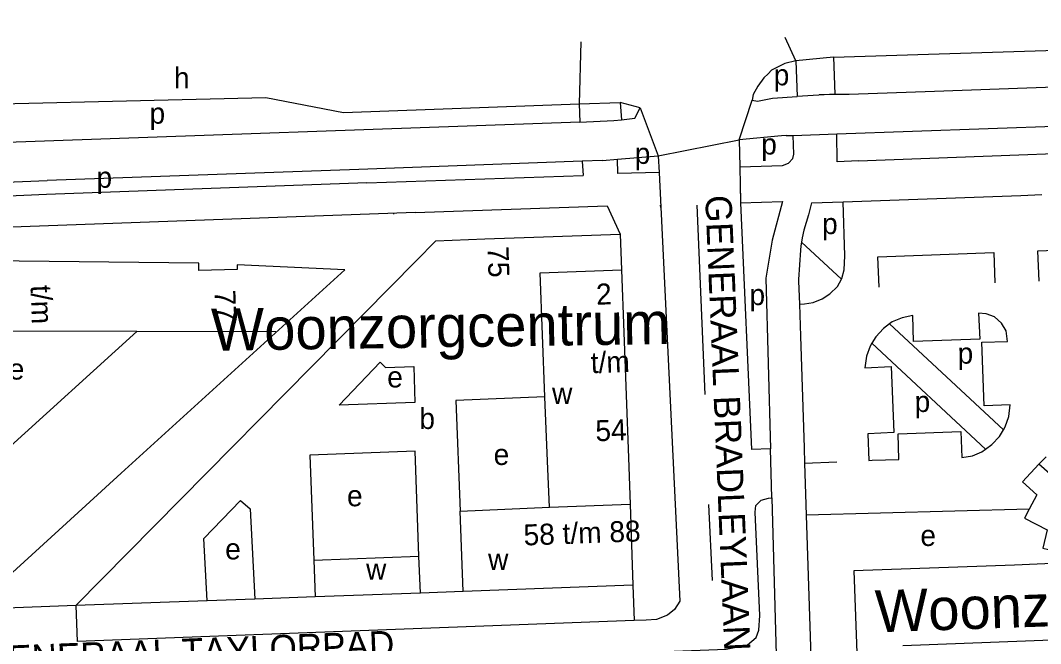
# Model space of a CAD drawing. Extents: x 159294 to 161936, y 384538 to 386517.
# Drawn here: x 161217.5 to 161411.8, y 386380.5 to 386499.3 of the extents above; entities that cross this region are included whole.
import ezdxf

# ---------------------------------------------------------------- set-up
doc = ezdxf.new("R2010")
doc.units = 0
for name, color, linetype in [('BLT_Basislijn', 7, 'Continuous'), ('BLT_Bebouwing', 7, 'Continuous'), ('BLT_Bebouwing_beschrifting', 7, 'Continuous'), ('BLT_Centroide', 7, 'Continuous'), ('BLT_Huisnummer_reeks', 7, 'Continuous'), ('BLT_Onderdoorgang_en_onderverdeling', 7, 'Continuous'), ('BLT_Onderverdeling_panden', 7, 'Continuous'), ('BLT_Straatnaam', 7, 'Continuous'), ('BLT_Vlakafsluiter', 7, 'Continuous')]:
    doc.layers.add(name, color=color, linetype=linetype)

msp = doc.modelspace()

# ---------------------------------------------------------------- linework, layer by layer
at = {"layer": 'BLT_Basislijn'}
for p, q in [((161372.32, 386492.27), (161365.2, 386491.56)), ((161365.2, 386491.56), (161365.4, 386484.75)), ((161372.32, 386492.27), (161372.58, 386485.17)), ((161359.9, 386489.08), (161360.56, 386489.75)), ((161391.6, 386485.79), (161500, 386489.72)), ((161372.58, 386485.17), (161365.4, 386484.75)), ((161369.65, 386485.15), (161372.58, 386485.17)), ((161323.9, 386483.33), (161331.75, 386483.6)), ((161356.83, 386484.07), (161357.87, 386483.84)), ((161324.03, 386479.85), (161174.09, 386474.55)), ((161330.52, 386480.19), (161331.96, 386480.27)), ((161373.01, 386477.62), (161424.25, 386479.43)), ((161363.33, 386477.28), (161364.7, 386477.33)), ((161364.7, 386477.33), (161373.01, 386477.62)), ((161354.38, 386476.46), (161354.5, 386471.33)), ((161331.18, 386472.78), (161338.98, 386473.45)), ((161324.51, 386472.4), (161281.95, 386470.85)), ((161328.38, 386472.54), (161324.51, 386472.4)), ((161324.51, 386472.4), (161324.65, 386469.66)), ((161328.38, 386472.54), (161331.18, 386472.78)), ((161354.5, 386471.33), (161354.66, 386464.49)), ((161281.95, 386470.85), (161222.58, 386468.71)), ((161283.47, 386468.31), (161324.65, 386469.66)), ((161339.13, 386470.29), (161343.07, 386388.54)), ((161283.47, 386468.31), (161222.43, 386466.04)), ((161354.58, 386468.28), (161354.66, 386464.49)), ((161354.58, 386468.28), (161354.66, 386464.49)), ((161374.22, 386464.69), (161408.02, 386465.9)), ((161408.02, 386465.9), (161412.02, 386466.04)), ((161292.69, 386462.61), (161329.27, 386463.89)), ((161292.69, 386462.61), (161329.27, 386463.89)), ((161292.69, 386462.61), (161329.27, 386463.89)), ((161339.45, 386463.6), (161339.38, 386464.02)), ((161346.3, 386464.05), (161347.82, 386427.93)), ((161368.17, 386464.48), (161367.62, 386462.2)), ((161368.17, 386464.48), (161374.22, 386464.69)), ((161374.49, 386454.39), (161374.22, 386464.69)), ((161292.69, 386462.61), (161217.61, 386459.92)), ((161292.69, 386462.61), (161217.61, 386459.92)), ((161292.69, 386462.61), (161217.61, 386459.92)), ((161288.46, 386462.46), (161288.68, 386462.47)), ((161288.46, 386462.46), (161288.68, 386462.47)), ((161288.46, 386462.46), (161288.68, 386462.47)), ((161217.61, 386459.92), (161153.14, 386457.6)), ((161366.28, 386457.01), (161373.87, 386449.95)), ((161411.29, 386455.33), (161425.23, 386455.84)), ((161374.39, 386451.68), (161374.49, 386454.39)), ((161380.81, 386454.17), (161402.9, 386455.04)), ((161381.04, 386448.43), (161380.81, 386454.17)), ((161402.9, 386455.04), (161403.11, 386449.22)), ((161411.51, 386449.56), (161411.29, 386455.33)), ((161373.1, 386448.56), (161373.87, 386449.95)), ((161373.87, 386449.95), (161373.94, 386450.08)), ((161373.94, 386450.08), (161374.39, 386451.68)), ((161365.7, 386449.53), (161365.85, 386445.14)), ((161371.64, 386447.13), (161373.1, 386448.56)), ((161368.48, 386445.48), (161370.22, 386446.19)), ((161370.22, 386446.19), (161371.64, 386447.13)), ((161365.85, 386445.14), (161366.84, 386445.22)), ((161365.85, 386445.14), (161366.05, 386439.08)), ((161366.84, 386445.22), (161368.48, 386445.48)), ((161385.4, 386442.58), (161383.54, 386441.77)), ((161387.44, 386443.01), (161385.4, 386442.58)), ((161387.62, 386438.05), (161387.44, 386443.01)), ((161401.44, 386443.33), (161399.97, 386443.46)), ((161399.97, 386443.46), (161400.2, 386438.5)), ((161403.01, 386442.72), (161401.44, 386443.33)), ((161404.36, 386441.53), (161403.01, 386442.72)), ((161381.85, 386440.54), (161380.43, 386438.95)), ((161383.04, 386441.41), (161381.85, 386440.54)), ((161383.54, 386441.77), (161383.04, 386441.41)), ((161383.04, 386441.41), (161404.72, 386421.21)), ((161405.22, 386440.07), (161404.36, 386441.53)), ((161380.43, 386438.95), (161379.66, 386437.72)), ((161400.2, 386438.5), (161387.62, 386438.05)), ((161405.52, 386438.03), (161405.22, 386440.07)), ((161379.31, 386437.16), (161378.61, 386435.22)), ((161379.66, 386437.72), (161379.31, 386437.16)), ((161379.66, 386437.72), (161401.31, 386417.55)), ((161400.58, 386437.89), (161405.52, 386438.03)), ((161401.02, 386425.81), (161400.58, 386437.89)), ((161378.61, 386435.22), (161378.35, 386433.04)), ((161378.35, 386433.04), (161383.31, 386433.27)), ((161383.31, 386433.27), (161383.85, 386420.7)), ((161405.98, 386425.98), (161401.02, 386425.81)), ((161405.72, 386423.73), (161405.98, 386425.98)), ((161405.06, 386421.79), (161405.72, 386423.73)), ((161383.85, 386420.7), (161378.89, 386420.46)), ((161384.65, 386420.47), (161396.61, 386420.89)), ((161396.61, 386420.89), (161396.8, 386415.95)), ((161403.96, 386419.95), (161404.72, 386421.21)), ((161404.72, 386421.21), (161405.06, 386421.79)), ((161378.89, 386420.46), (161379.08, 386415.39)), ((161384.78, 386415.53), (161384.65, 386420.47)), ((161402.48, 386418.44), (161403.96, 386419.95)), ((161360.59, 386408.26), (161360.34, 386417.57)), ((161398.83, 386416.25), (161400.6, 386417)), ((161400.6, 386417), (161401.31, 386417.55)), ((161401.31, 386417.55), (161402.48, 386418.44)), ((161366.85, 386414.85), (161372.99, 386415.11)), ((161366.85, 386414.85), (161367.04, 386408.93)), ((161379.08, 386415.39), (161379.69, 386415.42)), ((161379.69, 386415.42), (161384.78, 386415.53)), ((161396.8, 386415.95), (161398.83, 386416.25)), ((161412.83, 386416.07), (161411.48, 386414.68)), ((161360.59, 386408.26), (161361.54, 386373.43)), ((161367.04, 386408.93), (161367.17, 386404.93)), ((161409.64, 386406.09), (161367.17, 386404.93)), ((161367.17, 386404.93), (161370.28, 386310.44)), ((161334.16, 386391.59), (161334.41, 386384.87)), ((161228.06, 386387.74), (161208.26, 386386.99)), ((161228.06, 386387.74), (161228.31, 386380.85)), ((161262.15, 386388.96), (161253.08, 386388.64)), ((161334.41, 386384.87), (161228.31, 386380.85))]:
    msp.add_line(p, q, dxfattribs=at)
for points in [[(161372.32, 386492.27), (161390.44, 386492.84), (161416.88, 386493.67), (161439.86, 386494.39), (161446.32, 386494.78), (161454.6, 386495.69), (161461.78, 386497.02), (161465.73, 386497.73), (161469.07, 386497.93), (161479.57, 386497.86), (161482.6, 386498), (161484.26, 386498.26), (161490.87, 386499.25)], [(161365.2, 386491.56), (161363.09, 386491.03), (161360.56, 386489.75)], [(161359.9, 386489.08), (161359.11, 386488.3), (161357.94, 386486.72), (161357.06, 386485.11), (161356.83, 386484.07)], [(161372.58, 386485.17), (161375.33, 386485.2), (161391.6, 386485.79)], [(161189.81, 386482.75), (161264.26, 386484.53), (161279.03, 386481.7), (161323.9, 386483.33)], [(161323.9, 386483.33), (161324.03, 386479.85)], [(161331.75, 386483.6), (161331.96, 386480.27)], [(161335.55, 386482.61), (161331.75, 386483.6)], [(161357.87, 386483.84), (161360.74, 386484.42), (161365.4, 386484.75)], [(161334.51, 386480.62), (161335.55, 386482.61)], [(161377.12, 386472.5), (161512.84, 386477.56), (161512.8, 386478.56), (161511.17, 386480.21), (161509.82, 386482.52)], [(161324.03, 386479.85), (161330.52, 386480.19)], [(161331.96, 386480.27), (161334.51, 386480.62)], [(161363.33, 386477.28), (161362.45, 386477.24), (161354.38, 386476.46)], [(161354.5, 386471.33), (161362.63, 386471.58), (161363.81, 386472.04), (161364.59, 386472.9), (161364.82, 386473.77), (161364.7, 386477.33)], [(161377.12, 386472.5), (161373.07, 386472.3), (161373.01, 386477.62)], [(161338.98, 386473.45), (161339.13, 386470.29)], [(161339.13, 386470.29), (161331.26, 386470.05), (161331.18, 386472.78)], [(161200.63, 386467.87), (161222.58, 386468.71)], [(161222.43, 386466.04), (161200.71, 386465.12), (161200.29, 386465.76)], [(161329.27, 386463.89), (161331.75, 386458.53)], [(161354.66, 386464.49), (161362.65, 386464.74), (161360.65, 386457.34), (161359.46, 386450.13), (161360.34, 386417.57)], [(161354.66, 386464.49), (161356.73, 386417.45)], [(161367.62, 386462.2), (161367.14, 386460.75), (161366.73, 386459.27), (161366.41, 386457.78), (161366.28, 386457.01)], [(161366.28, 386457.01), (161366.16, 386456.27), (161366.06, 386455.45)], [(161366.06, 386455.45), (161365.69, 386449.89), (161365.7, 386449.53)], [(161366.05, 386439.08), (161366.75, 386417.77), (161366.85, 386414.85)], [(161360.34, 386417.57), (161356.73, 386417.45)], [(161357.61, 386381.61), (161358.13, 386383.03), (161358.33, 386385.81), (161357.46, 386405.52), (161357.58, 386406.81), (161358.55, 386407.79), (161359.98, 386408.2), (161360.59, 386408.26)], [(161348.52, 386407), (161349.26, 386392.49)], [(161343.07, 386388.54), (161342.06, 386386.96), (161340.73, 386385.9), (161338.67, 386385.08), (161336.64, 386384.96), (161334.41, 386384.87)], [(161299.16, 386377.4), (161351.92, 386379.42), (161355.96, 386380.23), (161357.61, 386381.61)]]:
    msp.add_lwpolyline(points, dxfattribs=at)
at = {"layer": 'BLT_Bebouwing'}
for p, q in [((161331.75, 386458.53), (161332, 386451.69)), ((161332, 386451.69), (161333.29, 386415.89)), ((161317.86, 386415.23), (161317.34, 386427.5)), ((161318.23, 386406.5), (161317.86, 386415.23)), ((161333.29, 386415.89), (161333.61, 386407.05)), ((161273.36, 386396.39), (161293.4, 386397.12)), ((161376.25, 386394.33), (161376.88, 386376.98)), ((161293.66, 386390.09), (161273.61, 386389.38)), ((161301.79, 386390.39), (161293.66, 386390.09))]:
    msp.add_line(p, q, dxfattribs=at)
for points in [[(161296.64, 386457.22), (161305.96, 386457.59), (161315.29, 386457.93)], [(161315.29, 386457.93), (161331.75, 386458.53)], [(161228.06, 386387.74), (161292.84, 386453.45), (161296.64, 386457.22)], [(161279.29, 386451.71), (161258.78, 386452.64), (161258.75, 386451.8), (161251.45, 386451.61), (161251.48, 386452.98), (161211.44, 386453.43), (161182.58, 386452.91), (161157.83, 386452.02)], [(161212.99, 386391.38), (161229.92, 386406.79), (161236.69, 386412.95), (161279.29, 386451.71)], [(161317.34, 386427.5), (161316.46, 386451.11), (161332, 386451.69)], [(161317.34, 386427.5), (161300.45, 386426.77), (161301.23, 386405.7)], [(161293.4, 386397.12), (161292.67, 386417.12), (161272.63, 386416.39), (161273.36, 386396.39)], [(161415.16, 386413.86), (161413.53, 386412.8), (161411.48, 386414.68), (161408.36, 386411.29), (161411.07, 386408.8), (161409.64, 386406.09)], [(161253.08, 386388.64), (161252.4, 386400.47), (161259.4, 386407.73), (161261.22, 386406.15), (161262.15, 386388.96)], [(161333.61, 386407.05), (161334.16, 386391.59)], [(161409.64, 386406.09), (161408.74, 386404.4), (161413.05, 386402.12), (161412.24, 386398.68), (161415.49, 386397.91), (161415.47, 386395.78), (161406.82, 386395.44), (161376.25, 386394.33)], [(161334.16, 386391.59), (161301.79, 386390.39)], [(161253.08, 386388.64), (161228.06, 386387.74)], [(161273.61, 386389.38), (161262.15, 386388.96)], [(161443.71, 386359.92), (161446.93, 386363.39), (161427.27, 386381.61), (161385.54, 386380.07)]]:
    msp.add_lwpolyline(points, dxfattribs=at)
msp.add_lwpolyline([(161287.04, 386433.09), (161292.4, 386433.28), (161292.59, 386426.42), (161278.2, 386425.9), (161285.99, 386434.12)], close=True, dxfattribs=at)
at = {"layer": 'BLT_Onderdoorgang_en_onderverdeling'}
for p, q in [((161273.36, 386396.39), (161273.61, 386389.38)), ((161293.66, 386390.09), (161293.4, 386397.12))]:
    msp.add_line(p, q, dxfattribs=at)
at = {"layer": 'BLT_Onderverdeling_panden'}
for p, q in [((161239.65, 386439.98), (161193.03, 386440.07)), ((161266.14, 386439.92), (161239.65, 386439.98)), ((161301.23, 386405.7), (161318.23, 386406.5)), ((161301.79, 386390.39), (161301.23, 386405.7))]:
    msp.add_line(p, q, dxfattribs=at)
for points in [[(161214.19, 386416.81), (161239.65, 386439.98)], [(161318.23, 386406.5), (161333.61, 386407.05)]]:
    msp.add_lwpolyline(points, dxfattribs=at)
at = {"layer": 'BLT_Vlakafsluiter'}
for p, q in [((161324.21, 386495.14), (161323.9, 386483.33)), ((161365.2, 386491.56), (161363.12, 386496.01)), ((161354.38, 386476.46), (161356.83, 386484.07)), ((161335.55, 386482.61), (161338.98, 386473.45)), ((161338.98, 386473.45), (161354.38, 386476.46))]:
    msp.add_line(p, q, dxfattribs=at)

# ---------------------------------------------------------------- texts
at = {"layer": 'BLT_Bebouwing_beschrifting'}
for rotation, p in [(0.8535, (161253.87, 386436.28)), (2, (161380.43, 386382.6))]:
    msp.add_text('Woonzorgcentrum', height=8, rotation=rotation, dxfattribs=at).set_placement(p)
at = {"layer": 'BLT_Centroide'}
for s, p in [('h', (161246.73, 386486.29)), ('p', (161360.96, 386486.87)), ('p', (161242.08, 386479.56)), ('p', (161358.59, 386473.68)), ('p', (161334.49, 386471.9)), ('p', (161231.98, 386467.35)), ('p', (161370.18, 386458.51)), ('p', (161356.35, 386444.98)), ('p', (161395.99, 386433.82)), ('e', (161215.27, 386430.79)), ('e', (161287.35, 386429.29)), ('w', (161318.75, 386426.15)), ('p', (161387.8, 386424.61)), ('b', (161293.47, 386421.37)), ('e', (161307.62, 386414.51)), ('e', (161279.69, 386406.64)), ('e', (161388.9, 386399.07)), ('e', (161256.49, 386396.51)), ('w', (161306.56, 386394.52)), ('w', (161283.32, 386392.66))]:
    msp.add_text(s, height=4, dxfattribs=at).set_placement(p)
at = {"layer": 'BLT_Huisnummer_reeks'}
for s, rotation, p in [('75', 272.064, (161306.44, 386456.12)), ('t/m', 272.064, (161219.41, 386448.73)), ('2', 2.0637, (161327.2, 386445.04)), ('77', 272.064, (161254.42, 386447.8)), ('t/m', 2.0637, (161326.19, 386432)), ('54', 2.0637, (161327.07, 386419.02)), ('58 t/m 88', 2.0634, (161313.39, 386399.16))]:
    msp.add_text(s, height=4, rotation=rotation, dxfattribs=at).set_placement(p)
at = {"layer": 'BLT_Straatnaam'}
for s, rotation, p in [('GENERAAL BRADLEYLAAN', 272.4119, (161347.91, 386465.85)), ('GENERAAL TAYLORPAD', 2.2363, (161210.08, 386374.89))]:
    msp.add_text(s, height=5, rotation=rotation, dxfattribs=at).set_placement(p)

doc.saveas('drawing.dxf')
